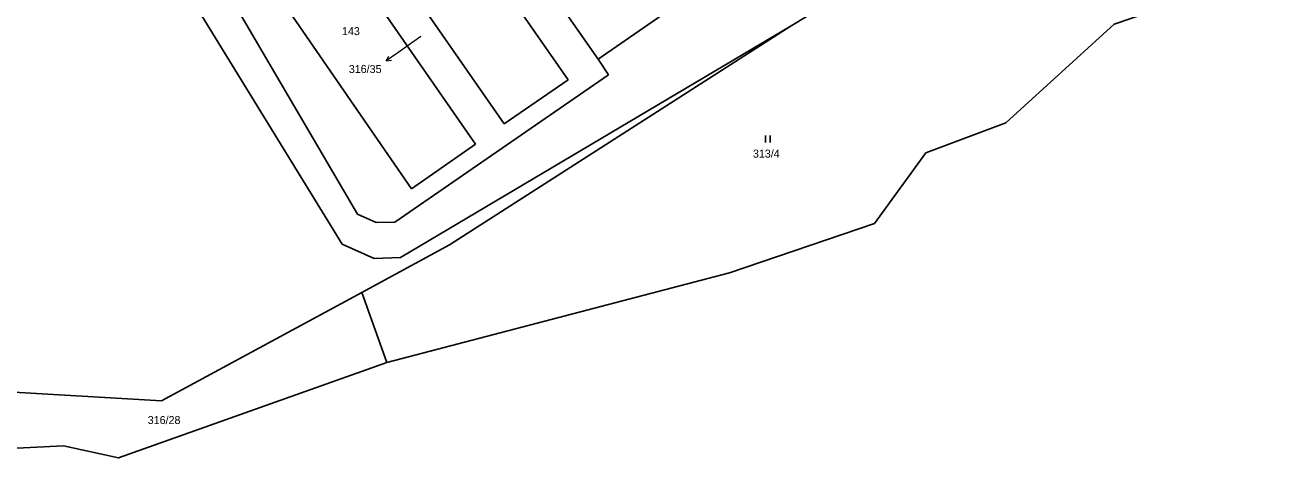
# Model space of a CAD drawing. Extents: x -765428 to -762163, y -1107632 to -1104975.
# Drawn here: x -763826.2 to -763559.8, y -1107133.3 to -1107041.4 of the extents above; entities that cross this region are included whole.
import ezdxf
from ezdxf.enums import TextEntityAlignment as Align

# ---------------------------------------------------------------- set-up
doc = ezdxf.new("R2010")
doc.units = 0
doc.header["$LTSCALE"] = 0.68
for name, color, linetype, lineweight in [('1', 7, 'Continuous', 25), ('3', 7, 'Continuous', 25), ('7', 7, 'Continuous', 13)]:
    doc.layers.add(name, color=color, linetype=linetype, lineweight=lineweight)
doc.layers.add('2', color=7, linetype='Continuous')

msp = doc.modelspace()

# ---------------------------------------------------------------- linework, layer by layer
at = {"layer": '1'}
for p, q in [((-763742.57, -1106993.8), (-763704.47, -1107048.59)), ((-763710.81, -1107052.97), (-763747.04, -1107000.7)), ((-763762.48, -1107007.46), (-763724.4, -1107062.35)), ((-763663.42, -1107041.51), (-763610.49, -1107009.22)), ((-763730.48, -1107066.67), (-763768.53, -1107011.75)), ((-763782.06, -1107021.07), (-763744.1, -1107076.13)), ((-763786.27, -1107029.08), (-763755.59, -1107081.51)), ((-763758.81, -1107087.9), (-763792.78, -1107032.62)), ((-763704.47, -1107048.59), (-763690.92, -1107039.24)), ((-763746.43, -1107090.74), (-763663.42, -1107041.51)), ((-763663.42, -1107041.51), (-763736, -1107088.06)), ((-763702.25, -1107051.93), (-763704.47, -1107048.59)), ((-763747.64, -1107083.23), (-763702.25, -1107051.93)), ((-763724.4, -1107062.35), (-763710.81, -1107052.97)), ((-763634.82, -1107068.52), (-763617.85, -1107062.1)), ((-763744.1, -1107076.13), (-763730.48, -1107066.67)), ((-763645.72, -1107083.51), (-763634.82, -1107068.52)), ((-763755.59, -1107081.51), (-763751.61, -1107083.3)), ((-763751.61, -1107083.3), (-763747.64, -1107083.23)), ((-763676.51, -1107093.99), (-763645.72, -1107083.51)), ((-763752.05, -1107090.97), (-763758.81, -1107087.9)), ((-763736, -1107088.06), (-763754.66, -1107098.17)), ((-763746.43, -1107090.74), (-763752.05, -1107090.97)), ((-763749.34, -1107113.05), (-763676.51, -1107093.99)), ((-763754.66, -1107098.17), (-763797.19, -1107121.2)), ((-763749.34, -1107113.05), (-763754.66, -1107098.17)), ((-763806.36, -1107133.31), (-763749.34, -1107113.05)), ((-763797.19, -1107121.2), (-763835.36, -1107118.94)), ((-763839.06, -1107131.83), (-763818, -1107130.74)), ((-763818, -1107130.74), (-763806.36, -1107133.31))]:
    msp.add_line(p, q, dxfattribs=at)
msp.add_lwpolyline([(-763617.85, -1107062.1), (-763594.82, -1107041.19), (-763574.19, -1107034.04), (-763559.82, -1107033.81)], dxfattribs=at)
at = {"layer": '3'}
for p, q in [((-763668.891, -1107066.29), (-763668.891, -1107064.79)), ((-763667.89, -1107066.29), (-763667.89, -1107064.79))]:
    msp.add_line(p, q, dxfattribs=at)
at = {"layer": '7'}
msp.add_line((-763749.468, -1107048.961), (-763748.361, -1107048.797), dxfattribs=at)
msp.add_lwpolyline([(-763742.09, -1107043.79), (-763747.01, -1107047.24), (-763749.468, -1107048.961), (-763748.935, -1107047.977)], dxfattribs=at)

# ---------------------------------------------------------------- texts
at = {"layer": '2'}
for s, p in [('143', (-763758.86, -1107043.485)), ('313/4', (-763671.56, -1107069.505)), ('316/28', (-763800.13, -1107126.115))]:
    msp.add_text(s, height=1.7, dxfattribs=at).set_placement(p)
msp.add_text('316/35', height=1.7, dxfattribs=at).set_placement((-763750.459, -1107051.535), align=Align.RIGHT)

doc.saveas('drawing.dxf')
